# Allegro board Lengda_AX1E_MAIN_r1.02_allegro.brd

Outline 234.8 x 122.7 mm; copper layers: TOP, GND02, ART03, GND04, PWR05, ART06, GND07, BOTTOM. Coordinates in mm from the lower left corner of the outline.

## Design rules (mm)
net group 50OHM: nets EDP_HPD PCH_PWROK
net group AUXN_LVDS: nets AUXN_LVDS EDP_AUX_DN
net group AUXP_LVDS: nets AUXP_LVDS EDP_AUX_DP
net group CL_CLK: nets CL_CLK N1637500
net group CL_DATA: nets CL_DATA N1637496
net group DMIC_CLK1: nets DMIC_CLK1 DMIC_CLK1_PCH
net group EDP_TX_DN<0>: nets EDP_TX_DN<0> TXN0_LVDS
net group EDP_TX_DN<1>: nets EDP_TX_DN<1> TXN1_LVDS
net group EDP_TX_DN<2>: nets EDP_TX_DN<2> N3431626
net group EDP_TX_DN<3>: nets EDP_TX_DN<3> N3431634
net group EDP_TX_DP<0>: nets EDP_TX_DP<0> TXP0_LVDS
net group EDP_TX_DP<1>: nets EDP_TX_DP<1> TXP1_LVDS
net group EDP_TX_DP<2>: nets EDP_TX_DP<2> N3431630
net group EDP_TX_DP<3>: nets EDP_TX_DP<3> N3431638
net group FLASH_SPI_D: nets FLASH_SPI_D<2> FLASH_SPI_D<3>
net group HDMI_CTRLCLK: nets HDMI_CTRLCLK N8275258
net group HDMI_CTRLDATA: nets HDMI_CTRLDATA N8275262
net group HSO: nets HSON HSOP
net group I2C_CLK1: nets I2C_CLK1 SMB_L1CLK_PCH
net group I2C_DATA1: nets I2C_DATA1 SMB_L1DATA_PCH
net group LAN_TX0N: nets LAN_TX0N N2478593
net group LAN_TX0P: nets LAN_TX0P N2478589
net group LAN_TX1N: nets LAN_TX1N N2478581
net group LAN_TX1P: nets LAN_TX1P N2478743
net group LAN_TX2N: nets LAN_TX2N N2478475
net group LAN_TX2P: nets LAN_TX2P N2478981
net group LAN_TX3N: nets LAN_TX3N N2479001
net group LAN_TX3P: nets LAN_TX3P N2478393
net group M_A_CKE: nets M_A_CKE<0> M_A_CKE<1>
net group M_A_CLK_DDR_DN#: nets M_A_CLK_DDR_DN#<0> M_A_CLK_DDR_DN#<1>
net group M_A_CLK_DDR_DP: nets M_A_CLK_DDR_DP<0> M_A_CLK_DDR_DP<1>
net group M_A_CS#: nets M_A_CS#<0> M_A_CS#<1>
net group M_A_ODT: nets M_A_ODT<0> M_A_ODT<1>
net group M_CNV_WR_0_D: nets CNV_WR_0_DN CNV_WR_0_DP
net group M_CNV_WR_1_D: nets CNV_WR_1_DN CNV_WR_1_DP
net group M_CNV_WR_CLK_D: nets CNV_WR_CLK_DN CNV_WR_CLK_DP
net group M_CNV_WT_0_D: nets CNV_WT_0_DN CNV_WT_0_DP
net group M_CNV_WT_1: nets CNV_WT_1_DN CNV_WT_1_DP
net group M_CNV_WT_CLK_D: nets CNV_WT_CLK_DN CNV_WT_CLK_DP
net group M_DDRA_CTL: nets M_0_CSA1_N M_0_CSB0_N
net group M_DDRB_CLK0: nets M_B_CLK_DDR_DN*<0> M_B_CLK_DDR_DP<0>
net group M_GFX_PCIE_CLK_: nets GFX_PCIE_CLK_N GFX_PCIE_CLK_P
net group M_LAN_PCIE_CLK: nets LAN_PCIE_CLK_DN LAN_PCIE_CLK_DP
net group M_PCIE_RX_D_1_WIFI: nets PCIE_RX_DN_9_WIFI PCIE_RX_DP_9_WIFI
net group M_PCIE_RX_D_5_GPU: nets PCIE_RX_DN_5_GPU PCIE_RX_DP_5_GPU
net group M_PCIE_RX_D_6_GPU: nets PCIE_RX_DN_6_GPU PCIE_RX_DP_6_GPU
net group M_PCIE_RX_D_7_GPU: nets PCIE_RX_DN_7_GPU PCIE_RX_DP_7_GPU
net group M_PCIE_RX_D_8_GPU: nets PCIE_RX_DN_8_GPU PCIE_RX_DP_8_GPU
net group M_PCIE_RX_D_9_SSD: nets PCIE_RX_DN_13_SSD PCIE_RX_DP_13_SSD
net group M_PCIE_RX_D_10_SSD: nets PCIE_RX_DN_14_SSD PCIE_RX_DP_14_SSD
net group M_PCIE_RX_D_11_SSD: nets PCIE_RX_DN_15_SSD PCIE_RX_DP_15_SSD
net group M_PCIE_RX_D_12_SSD: nets PCIE_RX_DN_16_SSD PCIE_RX_DP_16_SSD
net group M_PCIE_TX_D_12_SSD: nets PCIE_TX_DN_16_SSD PCIE_TX_DP_16_SSD
net group M_SSD_PCIE_CLK: nets SSD_PCIE_CLK_DN SSD_PCIE_CLK_DP
net group M_SSD_SATA_RX1: nets SSD_SATA_RXN1 SSD_SATA_RXP1
net group M_WIFI_PCIE_CLK: nets WIFI_PCIE_CLK_DN WIFI_PCIE_CLK_DP
net group MDI0: nets MDI0+ MDI0-
net group MDI1: nets MDI1+ MDI1-
net group MDI2: nets MDI2+ MDI2-
net group MDI3: nets MDI3+ MDI3-
net group N2010982: nets N2010982 N4072093
net group N5816815: nets N5816815 N5816861
net group NFC_I2C: nets SMBL0CLK_NFC SMBL0DATA_NFC
net group PCIE_TX_DN<10>: nets N5807743 PCIE_TX_DN<10>
net group PCIE_TX_DN_5_GPU: nets N5765083 PCIE_TX_DN_5_GPU
net group PCIE_TX_DN_6_GPU: nets N5765191 PCIE_TX_DN_6_GPU
net group PCIE_TX_DN_7_GPU: nets N5765627 PCIE_TX_DN_7_GPU
net group PCIE_TX_DN_8_GPU: nets N5765735 PCIE_TX_DN_8_GPU
net group PCIE_TX_DN_9_WIFI: nets N5807759 PCIE_TX_DN_9_WIFI
net group PCIE_TX_DN_13_SSD: nets N5766235 PCIE_TX_DN_13_SSD
net group PCIE_TX_DN_14_SSD: nets N5766259 PCIE_TX_DN_14_SSD
net group PCIE_TX_DN_15_SSD: nets N5766195 PCIE_TX_DN_15_SSD
net group PCIE_TX_DP<10>: nets N5807747 PCIE_TX_DP<10>
net group PCIE_TX_DP_5_GPU: nets N5765087 PCIE_TX_DP_5_GPU
net group PCIE_TX_DP_6_GPU: nets N5765195 PCIE_TX_DP_6_GPU
net group PCIE_TX_DP_7_GPU: nets N5765631 PCIE_TX_DP_7_GPU
net group PCIE_TX_DP_8_GPU: nets N5765739 PCIE_TX_DP_8_GPU
net group PCIE_TX_DP_9_WIFI: nets N5807763 PCIE_TX_DP_9_WIFI
net group PCIE_TX_DP_13_SSD: nets N5766239 PCIE_TX_DP_13_SSD
net group PCIE_TX_DP_14_SSD: nets N5766263 PCIE_TX_DP_14_SSD
net group PCIE_TX_DP_15_SSD: nets N5766199 PCIE_TX_DP_15_SSD
net group POWER: nets +V1P8S +V5S
net group SMB_CLK: nets SMB_CLK SMB_CLK_S2
net group SMB_DATA: nets SMB_DATA SMB_DATA_S2
net group SSD_SATA_RX0: nets N19848541 N19848543
net group SSD_SATA_TX0: nets N19848545 N19848547
net group SSD_SATA_TX1: nets SSD_SATA_TXN1 SSD_SATA_TXP1
net group USB2_DN: nets USB2_DN<1> USB2_DN<3>
net group USB2_DN0_CAM: nets USB2_DN0_CAM USB2_DN<5>
net group USB2_DN<4>: nets N2461749 USB2_DN<4>
net group USB2_DN<7>: nets N2447682 USB2_DN<7>
net group USB2_DN<9>: nets N2465519 USB2_DN<9>
net group USB2_DP: nets USB2_DP<1> USB2_DP<3>
net group USB2_DP0_CAM: nets USB2_DP0_CAM USB2_DP<5>
net group USB2_DP<4>: nets N2461741 USB2_DP<4>
net group USB2_DP<7>: nets N2447742 USB2_DP<7>
net group USB2_DP<9>: nets N2465511 USB2_DP<9>
net group USB3_RX_DN<1>: nets USB3_RX_DN<1> USB3_RX_DN<1>_C
net group USB3_RX_DN<2>: nets USB3_RX_DN<2> USB3_RX_DN<2>_C
net group USB3_RX_DP<1>: nets USB3_RX_DP<1> USB3_RX_DP<1>_C
net group USB3_RX_DP<2>: nets USB3_RX_DP<2> USB3_RX_DP<2>_C
net group USB3_TX_DN<2>_C: nets N2447932 USB3_TX_DN<2>_C
net group USB3_TX_DP<2>_C: nets N2447732 USB3_TX_DP<2>_C
net group DMIC_CLK0: nets DMIC_CLK0 DMIC_CLK0_PCH DMIC_CLK_CODEC N776559
net group DMIC_DATA0: nets DMIC_DATA0 DMIC_DATA0_PCH DMIC_DATA_CODEC N776947
net group DMIC_DATA1: nets DMIC_DATA1 DMIC_DATA1_PCH DMIC_DATA34_CODEC
net group HDA: nets HDA_BITCLK HDA_RST# HDA_SDATAIN0 HDA_SDATAOUT HDA_SYNC
net group HDMI_CLK+: nets HDMI_CLK+ OUT_CLK+ TMDS_CLKP
net group HDMI_CLK-: nets HDMI_CLK- N17228942 OUT_CLK- TMDS_CLKN
net group HDMI_D0+: nets HDMI_D0+ OUT_D0+ TMDS_DATAP0
net group HDMI_D0-: nets HDMI_D0- OUT_D0- TMDS_DATAN0
net group HDMI_D1+: nets HDMI_D1+ OUT_D1+ TMDS_DATAP1
net group HDMI_D1-: nets HDMI_D1- OUT_D1- TMDS_DATAN1
net group HDMI_D2+: nets HDMI_D2+ OUT_D2+ TMDS_DATAP2
net group HDMI_D2-: nets HDMI_D2- OUT_D2- TMDS_DATAN2
net group LCD_BA: nets LCD_BA<1> LCD_BA<2> LCD_BA<GND>
net group M_A_DQ: nets M_A_DQ<0> M_A_DQ<1> M_A_DQ<2> M_A_DQ<3> M_A_DQ<4> M_A_DQ<5> M_A_DQ<6> M_A_DQ<7> M_A_DQ<8> M_A_DQ<9> M_A_DQ<10> M_A_DQ<11> M_A_DQ<12> M_A_DQ<13> M_A_DQ<14> M_A_DQ<15> M_A_DQ<16> M_A_DQ<17> M_A_DQ<18> M_A_DQ<19> M_A_DQ<20> M_A_DQ<21> M_A_DQ<22> M_A_DQ<23> M_A_DQ<24> M_A_DQ<25> M_A_DQ<26> M_A_DQ<27> M_A_DQ<28> M_A_DQ<29> M_A_DQ<30> M_A_DQ<31> M_A_DQ<32> M_A_DQ<33> M_A_DQ<34> M_A_DQ<35> M_A_DQ<36> M_A_DQ<37> M_A_DQ<38> M_A_DQ<39> M_A_DQ<40> M_A_DQ<41> M_A_DQ<42> M_A_DQ<43> M_A_DQ<44> M_A_DQ<45> M_A_DQ<46> M_A_DQ<47> M_A_DQ<48> M_A_DQ<49> M_A_DQ<50> M_A_DQ<51> M_A_DQ<52> M_A_DQ<53> M_A_DQ<54> M_A_DQ<55> M_A_DQ<56> M_A_DQ<57> M_A_DQ<58> M_A_DQ<59> M_A_DQ<60> M_A_DQ<61> M_A_DQ<62> M_A_DQ<63>
net group M_A_DQS_DN#: nets M_A_DQS_DN#<0> M_A_DQS_DN#<1> M_A_DQS_DN#<2> M_A_DQS_DN#<3> M_A_DQS_DN#<4> M_A_DQS_DN#<5> M_A_DQS_DN#<7>
net group M_A_DQS_DP: nets M_A_DQS_DP<0> M_A_DQS_DP<1> M_A_DQS_DP<2> M_A_DQS_DP<3> M_A_DQS_DP<4> M_A_DQS_DP<5> M_A_DQS_DP<6> M_A_DQS_DP<7>
net group M_DDRA_CMD: nets DDR0_A_ALERT_N# DDR0_A_PARITY M_A_A0 M_A_A1 M_A_A2 M_A_A3 M_A_A4 M_A_A5 M_A_A6 M_A_A7 M_A_A8 M_A_A9 M_A_A10 M_A_A11 M_A_A12 M_A_A13 M_A_ACT_N M_A_BG0 M_A_BG1 M_A_BS0 M_A_BS1 M_A_CAS_N M_A_RAS_N M_A_WE_N
net group M_DDRA_DQS6: nets M_A_DQS_DN#<6>
net group M_DDRB_CLK1: nets M_B_CLK_DDR_DN*<1>
net group M_DDRB_CMD: nets DDR1_B_PARITY M_B_A0 M_B_A1 M_B_A2 M_B_A3 M_B_A4 M_B_A5 M_B_A6 M_B_A7 M_B_A8 M_B_A9 M_B_A10 M_B_A11 M_B_A12 M_B_A13 M_B_ACT_N M_B_BG0 M_B_BG1 M_B_BS0 M_B_BS1 M_B_CAS_N M_B_CSA1_N M_B_CSB0_N M_B_RAS_N M_B_WE_N
net group M_DDRB_CTL: nets M_B_CKE<0> M_B_CKE<1> M_B_CLK_DDR_DP<1> M_B_CS*<0> M_B_CS*<1> M_B_ODT<0> M_B_ODT<1>
net group M_DDRB_DATA0: nets M_B_DQ<0> M_B_DQ<1> M_B_DQ<2> M_B_DQ<3> M_B_DQ<4> M_B_DQ<5> M_B_DQ<6> M_B_DQ<7> M_B_DQS_DP<0>
net group M_DDRB_DATA1: nets M_B_DQ<8> M_B_DQ<9> M_B_DQ<10> M_B_DQ<11> M_B_DQ<12> M_B_DQ<13> M_B_DQ<14> M_B_DQ<15> M_B_DQS_DP<1>
net group M_DDRB_DATA2: nets M_B_DQ<16> M_B_DQ<17> M_B_DQ<18> M_B_DQ<19> M_B_DQ<20> M_B_DQ<21> M_B_DQ<22> M_B_DQ<23> M_B_DQS_DP<2>
net group M_DDRB_DATA3: nets M_B_DQ<24> M_B_DQ<25> M_B_DQ<26> M_B_DQ<27> M_B_DQ<28> M_B_DQ<29> M_B_DQ<30> M_B_DQ<31> M_B_DQS_DP<3>
net group M_DDRB_DATA4: nets M_B_DQ<32> M_B_DQ<33> M_B_DQ<34> M_B_DQ<35> M_B_DQ<36> M_B_DQ<37> M_B_DQ<38> M_B_DQ<39> M_B_DQS_DP<4>
net group M_DDRB_DATA5: nets M_B_DQ<40> M_B_DQ<41> M_B_DQ<42> M_B_DQ<43> M_B_DQ<44> M_B_DQ<45> M_B_DQ<46> M_B_DQ<47> M_B_DQS_DP<5>
net group M_DDRB_DATA6: nets M_B_DQ<48> M_B_DQ<49> M_B_DQ<50> M_B_DQ<51> M_B_DQ<52> M_B_DQ<53> M_B_DQ<54> M_B_DQ<55> M_B_DQS_DP<6>
net group M_DDRB_DATA7: nets M_B_DQ<56> M_B_DQ<57> M_B_DQ<58> M_B_DQ<59> M_B_DQ<60> M_B_DQ<61> M_B_DQ<62> M_B_DQ<63> M_B_DQS_DP<7>
net group M_DDRB_DQS0: nets M_B_DQS_DN*<0>
net group M_DDRB_DQS1: nets M_B_DQS_DN*<1>
net group M_DDRB_DQS2: nets M_B_DQS_DN*<2>
net group M_DDRB_DQS3: nets M_B_DQS_DN*<3>
net group M_DDRB_DQS4: nets M_B_DQS_DN*<4>
net group M_DDRB_DQS5: nets M_B_DQS_DN*<5>
net group M_DDRB_DQS6: nets M_B_DQS_DN*<6>
net group M_DDRB_DQS7: nets M_B_DQS_DN*<7>
net group M_LAO: nets LAO_CLKP LAO_DATAP0 LAO_DATAP1 LAO_DATAP2 LAO_DATAP3
net group M_LAO1: nets LAO1_CLKP LAO1_DATAP0 LAO1_DATAP1 LAO1_DATAP2 LAO1_DATAP3
net group M_LAO1_CLK: nets LAO1_CLKN
net group M_LAO1_DATA0: nets LAO1_DATAN0
net group M_LAO1_DATA1: nets LAO1_DATAN1
net group M_LAO1_DATA2: nets LAO1_DATAN2
net group M_LAO1_DATA3: nets LAO1_DATAN3
net group M_LAO_CLK: nets LAO_CLKN
net group M_LAO_DATA0: nets LAO_DATAN0
net group M_LAO_DATA1: nets LAO_DATAN1
net group M_LAO_DATA2: nets LAO_DATAN2
net group M_LAO_DATA3: nets LAO_DATAN3
net group PCIE: nets PLT_RST_BUF#
net group PCIE_RX_DN: nets PCIE_RX_DN<10>
net group PCIE_RX_DP: nets PCIE_RX_DP<10>
net group USB2_OC: nets USB2_OC<0> USB2_OC<1> USB2_OC<2> USB2_OC<3>
net group USB3_TX_DN: nets USB3_TX_DN<2>
net group USB3_TX_DN<1>: nets N1170323 USB3_TX_DN<1> USB3_TX_DN<1>_C
net group USB3_TX_DP: nets USB3_TX_DP<2>
net group USB3_TX_DP<1>: nets N1170159 USB3_TX_DP<1> USB3_TX_DP<1>_C
nets with their own width: min track width 0.203; nets GND

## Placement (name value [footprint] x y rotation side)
ACN1  WB1012US-02T5  [SMD-CN-100P-2N-V-CB]  155.78 112.13 90 top
C1  20PF  [CC0402N]  66.65 71.65 180 bottom
C2  1uF  [CC0402N]  155.92 92.15 0 top
C3  220nF  [CC0402N]  220.99 51.78 0 bottom
C4  1uF  [CC0402N]  155.86 94.8 270 top
C5  0.1uF  [CC0402N]  161.27 94.85 270 top
C6  10uF  [CC0603N]  32.05 68.8 0 top
C7  47UF  [CAE630W570HN]  123.97 64.68 0 top
C8  1uF  [CC0402N]  48.41 58.97 90 bottom
C9  0.1uF  [CC0402N]  49.64 58.97 270 bottom
C10  0.1uF  [CC0402N]  160.65 92.17 90 top
C11  15pF  [CC0402N]  164.63 85.57 270 top
C12  220nF  [CC0402N]  220.99 50.95 0 bottom
C13  15pF  [CC0402N]  165.89 85.56 270 top
C14  1uF  [CC0603N]  167.92 65.52 90 bottom
C15  1uF  [CC0603N]  167.11 57.89 270 bottom
C16  22uF  [CC0603N]  92 74.97 0 top
C17  0.1uF  [CC0402N]  88.24 86.82 0 top
C18  0.1uF  [CC0402N]  91.91 73.97 0 top
C19  100uF  [CAE660W800HN]  101.87 91.44 90 top
C20  4.7UF  [CC0603N]  94.85 85.24 270 top
C21  1uF  [CC0402N]  168.23 95.88 270 bottom
C22  1uF  [CC0402N]  213.21 71.15 180 bottom
C23  0.1uF  [CC0402N]  88.97 88.82 180 top
C24  0.1uF  [CC0402N]  88.97 89.59 180 top
C25  0.1uF  [CC0402N]  91.82 89.74 90 top
C26  4.7UF  [CC0603N]  90.47 89.99 270 top
C27  0.1uF  [CC0402N]  82.46 88.04 270 top
C28  0.1uF  [CC0402N]  83.24 93.09 90 top
C29  1uF  [CC0603N]  83.19 90.84 90 top
C30  1uF  [CC0402N]  92.6 89.74 270 top
C31  0.1uF  [CC0402N]  126.64 77.29 270 top
C32  22uF  [CC0603N]  134.78 82.22 90 bottom
C33  0.1uF  [CC0402N]  132.57 82.17 90 bottom
C34  22uF  [CC0603N]  179.04 98.7 90 bottom
C35  22uF  [CC0603N]  177.84 98.7 90 bottom
C36  22uF  [CC0603N]  169.25 90.14 180 bottom
C37  22uF  [CC0603N]  169.24 91.35 180 bottom
C38  22uF  [CC0603N]  178.24 100.48 90 top
C39  22uF  [CC0603N]  179.49 100.54 90 top
C40  22uF  [CC0603N]  199.8 85.84 90 bottom
C41  22uF  [CC0603N]  201.08 88.98 90 top
C42  22uF  [CC0603N]  202.44 88.97 90 top
C43  2.2uF  [CC0603N]  164.65 95.08 180 top
C44  0.1uF  [CC0402N]  165.01 94.06 180 top
C45  22uF  [CC0603N]  164.64 93.03 180 top
C46  18pF  [CC0402N]  171.94 58.4 270 bottom
C47  18pF  [CC0402N]  171.94 60.16 90 bottom
C48  22nF  [CC0402N]  218.23 62.88 0 bottom
C49  10UF  [CC0603N]  229.92 18.77 0 bottom
C50  0.1uF  [CC0402N]  155.95 86.68 0 top
C51  10uF  [CC0603N]  71.65 57.15 270 bottom
C52  10uF  [CC0603N]  76.21 58.6 270 bottom
C53  0.1uF  [CC0402N]  77.25 58.72 270 bottom
C54  22uF  [CC0603N]  184.96 90.8 0 bottom
C55  10uF  [CC0603N]  128.27 110.32 90 top
C56  0.1uF  [CC0402N]  130.06 110.38 270 top
C57  0.1uF  [CC0402N]  129.29 110.38 270 top
C58  10UF  [CC0603N]  128.94 89.86 270 top
C59  22uF  [CC0603N]  183.5 85.32 270 bottom
C60  220nF  [CC0402N]  220.92 49.42 0 bottom
C61  220nF  [CC0402N]  220.92 48.61 0 bottom
C62  220nF  [CC0402N]  220.96 46.21 0 bottom
C63  22uF  [CC0603N]  232.01 76.31 0 bottom
C64  0.1uF  [CC0402N]  132.18 86.36 0 top
C65  0.1uF  [CC0402N]  132.18 87.13 0 top
C66  220nF  [CC0402N]  220.95 45.41 0 bottom
C67  220nF  [CC0402N]  220.9 43.78 0 bottom
C68  10UF  [CC0603N]  45.24 83.49 270 bottom
C69  10UF  [CC0603N]  46.49 83.49 270 bottom
C70  0.1uF  [CC0402N]  45.4 79.81 90 bottom
C71  0.1uF  [CC0402N]  179.97 90.16 90 top
C72  0.1uF  [CC0402N]  179.19 90.16 90 top
C73  220nF  [CC0402N]  111.55 72.2 180 top
C74  220nF  [CC0402N]  111.55 71.43 180 top
C75  10UF  [CC0603N]  54.62 103.78 0 bottom
C76  10UF  [CC0603N]  54.38 94.61 90 bottom
C77  220nF  [CC0402N]  111.55 69.75 180 top
C78  220nF  [CC0402N]  111.55 68.96 180 top
C79  220nF  [CC0402N]  111.55 67.35 180 top
C80  0.1uF  [CC0402N]  130.71 89.99 90 top
C81  220nF  [CC0402N]  111.55 66.57 180 top
C82  10UF  [CC0603N]  55.66 94.61 90 bottom
C83  0.01uF  [CC0402N]  54.65 102.77 0 bottom
C84  10UF  [CC0603N]  57.9 111.81 90 top
C85  22nF  [CC0402N]  215.68 65.97 180 bottom
C86  10UF  [CC0603N]  115.08 50.74 90 bottom
C87  10UF  [CC0603N]  229.91 17.46 0 bottom
C88  0.1uF  [CC0402N]  98.32 55.4 90 top
C90  0.1uF  [CC0402N]  129.94 89.98 90 top
C104  22uF  [CC0603N]  155 84.88 270 top
C114  0.1uF  [CC0402N]  158.29 91.53 180 top
C118  0.1uF  [CC0402N]  124.07 60.55 0 top
C122  2.2uF  [CC0603N]  199.09 92.09 270 top
C123  0.1uF  [CC0402N]  198.07 92.37 270 top
C124  2.2uF  [CC0603N]  186.39 97.2 180 bottom
C125  0.1uF  [CC0402N]  185.62 81.79 90 bottom
C126  2.2uF  [CC0603N]  194.18 97.7 90 bottom
C127  1uF  [CC0402N]  159.96 50.18 90 bottom
C128  0.01uF  [CC0402N]  162.7 53.26 180 bottom
C129  4.7UF  [CC0603N]  116.18 63.58 180 top
C130  0.1uF  [CC0402N]  121.94 55.27 0 bottom
C131  0.1uF  [CC0402N]  113.87 50.98 90 bottom
C132  22uF  [CC0603N]  143.78 55.15 90 bottom
C133  220nF  [CC0402N]  220.9 42.98 0 bottom
C134  22uF  [CC0603N]  142.55 55.16 90 bottom
C135  0.1uF  [CC0402N]  197.79 70.66 270 bottom
C136  1uF  [CC0402N]  165.88 68.91 270 bottom
C137  1uF  [CC0402N]  229.69 19.77 180 bottom
C138  1uF  [CC0402N]  229.7 20.58 180 bottom
C139  100NF  [CC0402N]  224.49 9.23 90 top
C140  22uF  [CC0603N]  141.99 54.84 90 top
C141  2.2uF  [CC0603N]  223.48 8.96 90 top
C142  100NF  [CC0402N]  199.98 18.88 180 bottom
C143  10uF  [CC0603N]  118.83 89.21 270 bottom
C144  0.1uF  [CC0402N]  119.83 89.23 90 bottom
C145  0.01uF  [CC0402N]  15.01 110.48 270 top
C146  0.01uF  [CC0402N]  122.4 87.61 180 bottom
C147  10uF  [CC0603N]  125.89 90.04 270 bottom
C152  0.1uF  [CC0402N]  58.7 28.25 0 bottom
C153  0.1uF  [CC0402N]  58.7 29.04 0 bottom
C154  0.1uF  [CC0402N]  58.7 24.74 0 bottom
C155  0.1uF  [CC0402N]  58.7 25.53 0 bottom
C156  2.2uF  [CC0603N]  202.59 21.46 180 bottom
C157  100NF  [CC0402N]  182.34 21.83 0 bottom
C158  22uF  [CC0603N]  154.77 94.76 90 top
C159  22uF  [CC0603N]  152.3 94.76 90 top
C160  22uF  [CC0603N]  153.52 94.76 90 top
C161  10UF  [CC0603N]  176.53 14.96 90 bottom
C162  10UF  [CC0603N]  221.46 14.73 90 bottom
C163  10UF  [CC0603N]  213.69 14.96 90 bottom
C164  10UF  [CC0603N]  185.76 19.36 0 bottom
C165  10UF  [CC0603N]  167.11 14.91 90 bottom
C166  10UF  [CC0603N]  186.62 13.79 0 bottom
C167  10UF  [CC0603N]  171.81 19.1 90 bottom
C168  10UF  [CC0603N]  202.44 14.09 270 bottom
C169  1uF  [CC0402N]  182.38 19.22 90 bottom
C170  1uF  [CC0402N]  200.54 18.03 180 bottom
C171  1uF  [CC0402N]  175.34 18.77 270 bottom
C172  1uF  [CC0402N]  168.17 18.83 270 bottom
C173  1uF  [CC0402N]  172.98 14.79 90 bottom
C174  1uF  [CC0402N]  160.74 19.03 270 bottom
C175  1uF  [CC0402N]  195.93 17.96 90 bottom
C176  1uF  [CC0402N]  181.8 15.68 90 bottom
C177  10UF  [CC0603N]  224.87 22.52 0 bottom
C178  100NF  [CC0402N]  225.19 25.19 0 bottom
C179  100NF  [CC0402N]  225.19 23.57 0 bottom
C180  100NF  [CC0402N]  225.19 26 0 bottom
C181  100NF  [CC0402N]  225.17 24.37 0 bottom
C183  22uF  [CC0603N]  231.99 75.1 0 top
C184  22uF  [CC0603N]  192.11 92.12 270 top
C185  0.1uF  [CC0402N]  94.45 105.66 180 top
C187  0.1uF  [CC0402N]  61.69 31.07 0 bottom
C188  4.7UF  [CC0603N]  108.85 106.08 270 top
C189  4.7UF  [CC0603N]  107.6 106.06 270 top
C190  0.1uF  [CC0402N]  110.36 105.1 180 top
C191  0.01uF  [CC0402N]  76.04 61.13 90 bottom
C192  4.7UF  [CC0603N]  166.58 71.59 0 bottom
C193  22uF  [CC0603N]  145.01 55.12 90 bottom
C194  0.1uF  [CC0402N]  146.12 55.11 90 bottom
C195  1uF  [CC0402N]  113.4 57.38 270 bottom
C196  0.1uF  [CC0402N]  61.69 30.26 0 bottom
C197  0.1uF  [CC0402N]  110.92 50.85 180 bottom
C198  1uF  [CC0402N]  177.34 68.37 180 bottom
C199  100pF  [CC0402N]  110.85 48.8 180 bottom
C200  10uF  [CC0603N]  167.1 81.25 180 bottom
C201  22uF  [CC0603N]  184.9 92.15 0 bottom
C202  22uF  [CC0603N]  182.93 98.07 90 bottom
C205  10UF  [CC0603N]  144.32 75.72 270 top
C207  0.1uF  [CC0402N]  145.35 75.49 270 top
C209  10UF  [CC0603N]  149.7 72.69 270 top
C210  0.1uF  [CC0402N]  150.73 72.56 270 top
C211  10UF  [CC0603N]  221.44 8.33 270 bottom
C212  10UF  [CC0603N]  222.73 8.33 270 bottom
C213  0.1uF  [CC0402N]  223.77 8.29 270 bottom
C214  10UF  [CC0603N]  211.8 8.95 180 bottom
C215  0.1uF  [CC0402N]  164.52 53.24 180 bottom
C216  1uF  [CC0402N]  165.49 51.76 270 bottom
C217  10UF  [CC0603N]  127.48 70.97 0 bottom
C218  0.01uF  [CC0402N]  125.54 68.37 180 bottom
C219  10UF  [CC0603N]  125.57 69.42 0 bottom
C220  0.01uF  [CC0402N]  91.02 68.84 180 top
C222  10UF  [CC0603N]  91.09 69.97 0 top
C223  10UF  [CC0603N]  92.01 76.18 0 top
C224  0.01uF  [CC0402N]  119.22 68.72 0 bottom
C225  0.01uF  [CC0402N]  92 72.21 180 top
C226  10UF  [CC0603N]  133.57 82.22 90 bottom
C228  0.1uF  [CC0402N]  88.4 107.89 180 top
C229  0.1uF  [CC0402N]  86.73 108.37 90 top
C230  0.1uF  [CC0402N]  60.22 108.01 0 top
C231  0.1uF  [CC0402N]  62.72 107.94 0 top
C232  0.1uF  [CC0402N]  61.98 89.49 180 top
C233  0.1uF  [CC0402N]  21.28 91.79 270 bottom
C234  0.1uF  [CC0402N]  20.5 91.79 270 bottom
C235  22uF  [CC0603N]  180.45 97.99 90 bottom
C237  10uF  [CC0603N]  176.6 98.71 90 bottom
C238  10uF  [CC0603N]  180.71 85.55 270 bottom
C239  10uF  [CC0603N]  182.02 80.17 270 bottom
C240  10uF  [CC0603N]  175.37 98.72 90 bottom
C241  10uF  [CC0603N]  176.27 79.84 270 bottom
C242  10uF  [CC0603N]  169.56 88.83 180 bottom
C243  10UF  [CC0603N]  184.91 95.96 0 bottom
C244  10UF  [CC0603N]  178.5 85.57 270 bottom
C245  10UF  [CC0603N]  169.58 87.59 180 bottom
C246  10UF  [CC0603N]  180.75 80.18 270 bottom
C247  10UF  [CC0603N]  169.26 83.75 180 bottom
C248  10UF  [CC0603N]  169.69 86.2 180 bottom
C249  10UF  [CC0603N]  169.29 84.98 180 bottom
C250  10UF  [CC0603N]  184.96 89.6 0 bottom
C251  10UF  [CC0603N]  169.26 82.52 180 bottom
C252  100pF  [CC0402N]  179.71 79.95 90 bottom
C253  12pF  [CC0402N]  178.7 79.91 90 bottom
C254  0.1uF  [CC0402N]  177.78 79.84 90 bottom
C255  10uF  [CC0603N]  181.67 98 90 bottom
C256  10UF  [CC0603N]  174.13 98.72 90 bottom
C257  10UF  [CC0603N]  172.87 98.72 90 bottom
C258  10UF  [CC0603N]  198.67 80.68 270 bottom
C259  10UF  [CC0603N]  199.9 80.69 270 bottom
C260  10UF  [CC0603N]  197.36 80.68 270 bottom
C261  10UF  [CC0603N]  196.15 80.73 270 bottom
C262  0.1uF  [CC0402N]  160.09 90.38 270 top
C263  10UF  [CC0603N]  95.13 72.36 0 top
C264  10UF  [CC0603N]  95.13 73.58 0 top
C265  10UF  [CC0603N]  196.22 83.76 180 bottom
C266  10UF  [CC0603N]  210.35 79.19 90 bottom
C267  10UF  [CC0603N]  208.39 78.5 180 bottom
C268  10UF  [CC0603N]  184.89 93.46 0 bottom
C269  10UF  [CC0603N]  184.9 94.74 0 bottom
C270  1uF  [CC0402N]  185.52 84.31 180 bottom
C271  47uF  [CC0805N]  186.19 85.51 180 bottom
C272  10UF  [CC0603N]  193.34 80.71 90 bottom
C273  10UF  [CC0603N]  192.11 80.71 90 bottom
C274  1uF  [CC0402N]  211.68 69.39 270 bottom
C275  22uF  [CC0603N]  203.7 58.39 270 bottom
C276  22uF  [CC0603N]  209.96 58.28 270 bottom
C277  220nF  [CC0402N]  178.41 90.16 270 top
C278  220nF  [CC0402N]  177.64 90.16 270 top
C279  10uF  [CC0603N]  24.79 85.64 0 top
C280  22uF  [CC0603N]  206.48 58.39 270 bottom
C281  0.1uF  [CC0402N]  160.29 88.67 180 top
C282  10uF  [CC0603N]  35.83 68.67 0 top
C283  10UF  [CC0603N]  198.55 58.34 270 bottom
C284  10UF  [CC0603N]  189.73 68.63 180 bottom
C285  10UF  [CC0603N]  190.86 58.2 270 bottom
C286  10UF  [CC0603N]  193.38 58.33 270 bottom
C287  10UF  [CC0603N]  201.3 58.47 270 bottom
C288  1uF  [CC0402N]  196.44 68.65 180 bottom
C289  1uF  [CC0402N]  186.81 59.83 270 bottom
C290  1uF  [CC0402N]  209.54 62.94 90 bottom
C291  10uF  [CC0603N]  232.08 86.33 0 bottom
C295  0.1uF  [CC0402N]  156.98 87.6 180 top
C296  1uF  [CC0402N]  204.46 63.01 90 bottom
C297  1uF  [CC0402N]  194.52 62.94 90 bottom
C298  1uF  [CC0402N]  207.13 62.94 90 bottom
C299  12pF  [CC0402N]  199.51 63.01 270 bottom
C300  12pF  [CC0402N]  202.02 63.08 270 bottom
C301  12pF  [CC0402N]  196.97 62.94 270 bottom
C302  12pF  [CC0402N]  190.9 60.85 0 bottom
C303  12pF  [CC0402N]  199.26 68.58 0 bottom
C304  12pF  [CC0402N]  209.87 61.44 180 bottom
C305  1uF  [CC0402N]  187.06 62.94 90 bottom
C306  1uF  [CC0402N]  188.9 62.92 90 bottom
C307  1uF  [CC0402N]  189.91 62.92 90 bottom
C308  0.1uF  [CC0402N]  166.68 68.91 270 bottom
C309  1uF  [CC0402N]  197.36 61.38 0 bottom
C310  1uF  [CC0402N]  188.62 61.19 180 bottom
C311  1uF  [CC0402N]  212.08 62.82 90 bottom
C312  1uF  [CC0402N]  202 68.61 180 bottom
C313  22uF  [CC0603N]  179.91 77.65 180 bottom
C314  22uF  [CC0603N]  197.02 92.53 270 top
C315  22uF  [CC0603N]  195.81 92.52 270 top
C316  1uF  [CC0402N]  198.57 70.66 90 bottom
C317  1uF  [CC0402N]  193.15 68.61 0 bottom
C318  1uF  [CC0402N]  211.1 58.97 315 top
C319  1uF  [CC0402N]  205.27 61.21 0 bottom
C320  1uF  [CC0402N]  207.59 59.66 315 top
C321  1uF  [CC0402N]  202.22 59.81 270 top
C322  10UF  [CC0603N]  43.53 109.65 90 top
C323  10UF  [CC0603N]  35.51 109.98 90 top
C324  10UF  [CC0603N]  99.27 81.51 270 top
C325  1uF  [CC0402N]  213.59 59.78 315 top
C326  1uF  [CC0402N]  199.79 59.41 270 top
C327  1uF  [CC0402N]  197.31 59.85 270 top
C328  1uF  [CC0402N]  194.77 59.8 270 top
C329  1uF  [CC0402N]  192.13 59.78 270 top
C330  10UF  [CC0603N]  100.49 81.52 270 top
C331  1uF  [CC0402N]  125.07 77.31 90 top
C332  1000pF  [CC0402N]  123.51 77.31 270 top
C333  1uF  [CC0402N]  121.98 77.31 90 top
C334  1uF  [CC0402N]  189.75 59.81 270 top
C335  0.1uF  [CC0402N]  143.22 96.82 270 top
C336  22uF  [CC0603N]  149.97 84.92 270 top
C337  1uF  [CC0603N]  32.05 70.33 180 top
C338  22uF  [CC0603N]  151.21 84.93 270 top
C339  1uF  [CC0603N]  24.79 86.86 180 top
C340  0.1uF  [CC0402N]  40.71 59.87 180 top
C341  0.1uF  [CC0402N]  59.09 75.09 90 top
C342  47pF  [CC0402N]  38.98 61.71 270 top
C343  22uF  [CC0603N]  152.47 84.94 270 top
C344  22uF  [CC0603N]  153.72 84.94 270 top
C345  4.7UF  [CC0603N]  150.65 95.35 270 top
C346  4.7UF  [CC0603N]  149.41 95.35 270 top
C347  1uF  [CC0402N]  186.54 59.93 270 top
C348  1uF  [CC0402N]  184.56 59.93 270 top
C349  1uF  [CC0402N]  144.26 100.25 270 top
C350  1uF  [CC0402N]  150.81 99.97 270 top
C351  1000pF  [CC0402N]  146.59 100.25 90 top
C352  1uF  [CC0402N]  147.38 100.25 270 top
C353  1uF  [CC0402N]  181.95 58.08 270 bottom
C354  1uF  [CC0402N]  162.83 94.85 90 top
C355  1uF  [CC0402N]  162.05 94.85 90 top
C356  1uF  [CC0402N]  160.88 90.39 90 top
C357  1uF  [CC0402N]  163.26 91.51 0 top
C358  1uF  [CC0402N]  174.24 75.47 270 bottom
C359  1uF  [CC0402N]  174.89 68.72 90 bottom
C360  0.1uF  [CC0402N]  172.13 68.25 90 bottom
C361  1uF  [CC0402N]  200.18 70.68 90 bottom
C362  1uF  [CC0402N]  186.83 68.83 90 bottom
C363  1uF  [CC0402N]  224.19 70.59 90 top
C364  1uF  [CC0402N]  224.99 70.56 90 top
C365  1uF  [CC0402N]  199.39 70.67 90 bottom
C366  1uF  [CC0402N]  214.21 79.96 270 bottom
C367  0.1uF  [CC0402N]  50.49 80.51 90 top
C368  0.1uF  [CC0402N]  51.26 80.51 90 top
C369  0.1uF  [CC0402N]  53.02 80.51 90 top
C370  0.1uF  [CC0402N]  53.79 80.51 90 top
C371  0.1uF  [CC0402N]  55.56 80.51 90 top
C372  0.1uF  [CC0402N]  56.33 80.51 90 top
C373  0.1uF  [CC0402N]  58.08 80.51 90 top
C374  0.1uF  [CC0402N]  58.85 80.51 90 top
C375  1uF  [CC0603N]  35.83 67.46 180 top
C376  4.7UF  [CC0603N]  28.11 86.67 90 top
C377  1uF  [CC0402N]  201 70.66 90 bottom
C378  4.7UF  [CC0603N]  26.89 86.67 90 top
C379  15pF  [CC0402N]  203.12 78.24 90 bottom
C380  1uF  [CC0402N]  191.72 70.68 90 bottom
C381  4.7UF  [CC0603N]  116.22 62.2 180 top
C382  10UF  [CC0603N]  36.71 109.98 90 top
C383  1uF  [CC0402N]  226.64 70.56 90 top
C384  1uF  [CC0402N]  192.48 70.67 90 bottom
C385  0.01uF  [CC0402N]  42.54 109.94 90 top
C386  0.1uF  [CC0402N]  32.06 91.69 270 bottom
C387  0.1uF  [CC0402N]  31.25 91.69 270 bottom
C388  1uF  [CC0402N]  216.04 82.94 0 bottom
C389  15pF  [CC0402N]  202.34 78.24 90 bottom
C390  10UF  [CC0603N]  141.07 48.34 90 top
C391  22uF  [CC0603N]  201.86 97.9 90 bottom
C392  22uF  [CC0603N]  195.73 97.75 90 bottom
C393  10UF  [CC0603N]  142.31 48.34 90 top
C394  0.01uF  [CC0402N]  127.1 73.31 180 bottom
C395  10UF  [CC0603N]  127.48 72.22 0 bottom
C396  0.1uF  [CC0402N]  146.46 70.51 0 top
C397  22uF  [CC0603N]  212.19 97.68 90 bottom
C398  1uF  [CC0402N]  147.34 75.2 0 top
C399  0.01uF  [CC0402N]  145.81 72.9 90 top
C400  1uF  [CC0402N]  147.23 69.67 0 top
C401  0.01uF  [CC0402N]  119.83 74.21 0 bottom
C402  22uF  [CC0603N]  231.98 71.28 0 bottom
C403  22uF  [CC0603N]  179.92 76.31 180 bottom
C404  22uF  [CC0603N]  231.98 73.84 0 bottom
C405  15pF  [CC0402N]  201.56 78.24 90 bottom
C406  15pF  [CC0402N]  197.33 78.28 90 bottom
C407  10UF  [CC0603N]  51.09 111.39 90 top
C408  0.1uF  [CC0402N]  92.93 106.9 270 top
C409  0.1uF  [CC0402N]  94.45 106.45 180 top
C410  10UF  [CC0603N]  49.88 111.39 90 top
C411  0.1uF  [CC0402N]  212.25 9.95 180 bottom
C412  0.01uF  [CC0402N]  56.89 111.61 90 top
C413  20PF  [CC0402N]  66.65 70.43 180 bottom
C414  10uF  [CC0603N]  72.88 57.16 270 bottom
C415  0.1uF  [CC0402N]  70.2 61.83 90 bottom
C416  0.1uF  [CC0402N]  77.22 72.85 0 bottom
C417  0.1uF  [CC0402N]  77.22 72.07 0 bottom
C418  0.1uF  [CC0402N]  69.87 74.33 90 bottom
C419  0.1uF  [CC0402N]  70.2 57.36 270 bottom
C420  4.7uF  [CC0603N]  69.92 63.91 180 bottom
C421  0.1uF  [CC0402N]  69.91 65.94 270 bottom
C422  0.1uF  [CC0402N]  77.52 67.05 180 bottom
C423  0.1uF  [CC0402N]  77.52 67.87 180 bottom
C424  0.1uF  [CC0402N]  74.23 74.93 90 bottom
C425  0.1uF  [CC0402N]  75.8 74.92 90 bottom
C426  0.1uF  [CC0402N]  66.65 73.2 180 bottom
C427  0.1uF  [CC0402N]  63.02 67.88 180 bottom
C428  0.1uF  [CC0402N]  75 74.93 90 bottom
C429  22pF  [CC0402N]  38.18 83.13 90 top
C430  22pF  [CC0402N]  38.79 81.86 0 top
C431  22pF  [CC0402N]  35.66 79.78 180 top
C432  0.1uF  [CC0402N]  33.79 63.66 180 top
C433  0.1uF  [CC0402N]  66.65 72.43 180 bottom
C434  0.1uF  [CC0402N]  71.52 74.95 90 bottom
C435  4.7uF  [CC0603N]  63.01 66.08 0 bottom
C436  0.1uF  [CC0402N]  63.01 67.1 180 bottom
C437  1uF  [CC0402N]  71.45 65.94 90 bottom
C438  0.1uF  [CC0402N]  70.68 65.94 270 bottom
C439  15pF  [CC0402N]  196.55 78.28 90 bottom
C440  0.1uF  [CC0402N]  83.14 91.74 90 bottom
C441  0.01uF  [CC0402N]  80.94 91.74 270 bottom
C442  1000pF  [CC1206N]  80.93 91.71 270 bottom
C443  1000pF  [CC0402N]  82.35 91.74 90 bottom
C444  10UF  [CC0603N]  23.71 59.81 0 top
C445  0.1uF  [CC0402N]  23.7 60.8 180 top
C446  10UF  [CC0603N]  23.71 58.6 0 top
C449  0.1uF  [CC0402N]  233.17 52.69 90 top
C450  4.7UF  [CC0603N]  233.1 20.42 0 bottom
C451  0.01uF  [CC0402N]  20.36 42.71 180 top
C452  0.01uF  [CC0402N]  20.36 43.5 180 top
C453  0.01uF  [CC0402N]  20.4 46.55 180 top
C454  0.01uF  [CC0402N]  20.4 47.35 180 top
C455  4.7UF  [CC0603N]  233.15 27.58 0 bottom
C456  2.2uF  [CC0603N]  23.64 81.84 0 top
C457  2.2uF  [CC0603N]  24.89 77.42 180 top
C458  10UF  [CC0603N]  23.64 83.07 180 top
C459  0.1uF  [CC0603N]  233.15 28.79 180 bottom
C461  10UF  [CC0603N]  25.12 74.15 90 top
C462  0.1uF  [CC0402N]  24.67 76.22 0 top
C463  0.1uF  [CC0402N]  26.63 83.13 270 top
C464  10UF  [CC0603N]  24.4 84.3 0 top
C465  2.2uF  [CC0603N]  230.52 101.64 0 bottom
C467  1uF  [CC0603N]  22.69 75.44 270 top
C468  0.1uF  [CC0402N]  27.97 74.92 0 top
C469  10UF  [CC0603N]  28.3 73.92 180 top
C470  4.7UF  [CC0603N]  30.54 86.67 90 top
C471  4.7UF  [CC0603N]  29.3 86.67 90 top
C472  10UF  [CC0603N]  26.34 74.15 90 top
C473  0.1uF  [CC0603N]  232.49 35.23 180 top
C474  0.1uF  [CC0603N]  232.49 36.44 180 top
C475  10UF  [CC0603N]  33.01 87.74 270 top
C476  0.1uF  [CC0402N]  30.15 75.14 180 top
C477  10UF  [CC0603N]  30.54 72.74 90 top
C478  100pF  [CC0402N]  32.88 90.89 270 top
C479  0.1uF  [CC0402N]  34.1 87.43 270 top
C480  0.1uF  [CC0402N]  32.17 75.14 0 top
C481  10UF  [CC0603N]  32.17 72.75 90 top
C482  10UF  [CC0603N]  35.71 75.52 0 top
C483  0.1uF  [CC0402N]  35.44 76.51 180 top
C484  10UF  [CC0603N]  36.35 83.08 0 top
C485  0.1uF  [CC0402N]  35.89 82.09 180 top
C486  10pF  [CC0402N]  37.07 77.56 270 top
C487  10UF  [CC0603N]  36.36 80.91 180 top
C488  22pF  [CC0402N]  38.6 79.7 270 top
C491  0.1uF  [CC0402N]  232.59 43.61 270 top
C493  4.7UF  [CC0603N]  229.68 60.96 180 bottom
C494  0.1uF  [CC0603N]  232.96 63.11 180 bottom
C495  0.1uF  [CC0603N]  232.96 61.86 180 bottom
C496  10uF  [CC1210N]  55.06 45.21 180 top
C497  10uF  [CC1210N]  55.06 42.21 180 top
C499  100pF  [CC0402N]  21.77 87.02 180 top
C500  100pF  [CC0402N]  19.6 87.01 0 top
C501  100pF  [CC0402N]  12.08 92.96 270 top
C502  100pF  [CC0402N]  8.25 92.13 270 bottom
C503  0.1uF  [CC0603N]  54.29 39.41 0 top
C504  4.7uF  [CC1206N]  67.36 20.96 0 top
C505  10uF  [CC1210N]  67.36 24.85 0 top
C506  10uF  [CC5750N]  67.36 24.82 0 top
C507  0.1uF  [CC0402N]  31.47 51.61 180 bottom
C509  0.47uF  [CC0402N]  34.59 45.8 180 bottom
C512  2.2uF  [CC0402N]  33.33 47.85 180 bottom
C513  15pF  [CC0402N]  200.78 78.25 90 bottom
C514  0.1uF  [CC0402N]  56.19 15.07 180 bottom
C515  10UF  [CC0603N]  56.16 13.24 0 bottom
C516  15pF  [CC0402N]  195.77 78.29 90 bottom
C517  10UF  [CC0603N]  59.18 13.24 0 bottom
C518  0.01uF  [CC0402N]  55.07 10.43 90 bottom
C519  15pF  [CC0402N]  194.99 78.3 90 bottom
C520  0.1uF  [CC0402N]  57.4 9.83 0 bottom
C521  10uF  [CC0603N]  116.99 49.34 270 bottom
C522  1uF  [CC0603N]  118.26 49.34 270 bottom
C524  0.1uF  [CC0402N]  126.16 52.98 270 bottom
C525  10uF  [CC0603N]  125.16 52.86 90 bottom
C526  0.1uF  [CC0402N]  215.17 101.46 180 bottom
C531  0.1uF  [CC0402N]  52.54 30.73 270 bottom
C532  0.1uF  [CC0402N]  52.56 30.73 270 top
C534  2.2uF  [CC0603N]  65.24 25.14 180 bottom
C535  1uF  [CC0402N]  58.66 22.37 180 bottom
C536  0.1uF  [CC0402N]  61.06 18.5 270 bottom
C537  0.1uF  [CC0402N]  56.19 14.27 180 bottom
C540  0.1uF  [CC0402N]  47.2 26.39 0 bottom
C541  1uF  [CC0402N]  58.01 26.86 270 bottom
C542  0.1uF  [CC0402N]  59.3 26.86 270 bottom
C543  0.01uF  [CC0402N]  60.08 26.86 270 bottom
C544  10UF  [CC0603N]  58.32 20.26 270 bottom
C545  0.1uF  [CC0402N]  56.64 32.37 270 top
C546  0.1uF  [CC0402N]  48.09 16.64 0 bottom
C547  10uF  [CC0603N]  48.01 17.66 180 bottom
C548  10UF  [CC0603N]  52.53 17.7 180 bottom
C549  0.1uF  [CC0402N]  52.94 19.15 0 bottom
C550  0.01uF  [CC0402N]  52.94 19.94 0 bottom
C634  10uF  [CC0603N]  25.49 56.63 270 top
C635  1uF  [CC0603N]  24.27 56.62 90 top
C640  0.1uF  [CC0402N]  232.67 15.89 180 top
C641  0.1uF  [CC0402N]  232.77 26.72 0 top
C642  1000pF  [CC0402N]  231.1 21.13 180 top
C695  22uF  [CC0603N]  232.08 86.33 0 top
C696  22uF  [CC0603N]  232.01 81.33 0 bottom
C697  22uF  [CC0603N]  201.12 92.08 270 top
C698  22uF  [CC0603N]  232.01 78.78 0 bottom
C699  22uF  [CC0603N]  200.56 97.89 90 bottom
C700  22uF  [CC0603N]  232.02 77.54 0 top
C701  22uF  [CC0603N]  179.93 73.73 180 bottom
C702  10uF  [CC0603N]  232.1 88.76 0 top
C703  10uF  [CC0603N]  227.75 70.57 270 top
C704  10uF  [CC0603N]  232.01 80.02 0 top
C705  10uF  [CC0603N]  230.26 70.55 270 top
C706  10uF  [CC0603N]  199.21 97.9 90 bottom
C707  10uF  [CC0603N]  232.01 72.61 0 top
C708  10UF  [CC0603N]  194.59 92.52 270 top
C709  10UF  [CC0603N]  179.92 75.02 180 bottom
C710  10UF  [CC0603N]  210.87 97.7 90 bottom
C711  10UF  [CC0603N]  193.35 92.14 270 top
C712  10UF  [CC0603N]  205.79 92.21 270 top
C713  10UF  [CC0603N]  190.86 92.38 270 top
C714  1uF  [CC0402N]  218.3 70.12 90 bottom
C715  1uF  [CC0402N]  218.67 74.66 180 bottom
C716  1uF  [CC0402N]  219.16 70.07 90 bottom
C717  1uF  [CC0402N]  212.79 72.44 90 bottom
C718  1uF  [CC0402N]  216.28 80.77 270 bottom
C719  1uF  [CC0402N]  218.64 76.59 180 bottom
C720  1uF  [CC0402N]  196.18 70.68 90 bottom
C721  1uF  [CC0402N]  196.98 70.68 90 bottom
C722  1uF  [CC0402N]  216.51 69.98 90 bottom
C723  1uF  [CC0402N]  220.25 70.51 90 bottom
C724  1uF  [CC0402N]  183.56 68.81 90 bottom
C725  1uF  [CC0402N]  184.6 68.8 90 bottom
C726  1uF  [CC0402N]  181.7 68.77 90 bottom
C727  1uF  [CC0402N]  218.13 80.64 270 bottom
C798  10UF  [CC0603N]  14 110.67 270 top
C877  0.1u  [CC0402N]  140.37 68.05 180 top
C878  0.1u  [CC0402N]  137.11 68.05 180 top
C879  10UF  [CC0603N]  226.1 8.76 270 bottom
C880  10UF  [CC0603N]  224.84 8.78 270 bottom
C881  1uF  [CC0402N]  227.86 8.93 90 bottom
C882  1uF  [CC0402N]  227.07 8.93 90 bottom
C883  0.1uF  [CC0402N]  230.12 28.1 270 bottom
C884  2.2uF  [CC0603N]  228.75 28.36 270 bottom
C885  0.1uF  [CC0402N]  202.44 31.43 180 bottom
C886  2.2uF  [CC0603N]  202.51 32.44 180 bottom
C887  0.1uF  [CC0402N]  184.74 33.84 90 bottom
C888  10UF  [CC0603N]  211.49 25.92 270 bottom
C889  10UF  [CC0603N]  200.01 23.77 90 bottom
C890  10UF  [CC0603N]  163.46 26.23 90 bottom
C891  10UF  [CC0603N]  221.42 25.44 90 bottom
C892  10UF  [CC0603N]  217.03 20.05 180 bottom
C893  10UF  [CC0603N]  173.75 29.22 270 bottom
C894  10UF  [CC0603N]  162.25 30.47 270 bottom
C895  10UF  [CC0603N]  192.03 30.15 0 bottom
C896  1uF  [CC0402N]  169.87 26.63 90 bottom
C897  1uF  [CC0402N]  201.15 26.22 270 bottom
C898  1uF  [CC0402N]  178.75 30.43 270 bottom
C899  1uF  [CC0402N]  189.37 32.49 270 bottom
C900  1uF  [CC0402N]  190.35 28.5 180 bottom
C901  1uF  [CC0402N]  175.04 29.36 270 bottom
C902  1uF  [CC0402N]  198.97 24.03 90 bottom
C903  1uF  [CC0402N]  178.41 25.76 270 bottom
C904  10UF  [CC0603N]  225.76 13.54 0 bottom
C905  0.1uF  [CC0402N]  225.37 17.02 0 bottom
C906  0.1uF  [CC0402N]  225.38 16.24 0 bottom
C907  0.1uF  [CC0402N]  225.37 14.62 0 bottom
C908  0.1uF  [CC0402N]  225.37 15.44 0 bottom
C3218  0.1uF_25V_0603  [CC0603N]  99.69 109.25 90 bottom
C6036  10UF  [CC0603N]  22.18 108.65 180 top
C6037  10UF  [CC0603N]  22.18 107.43 180 top
C6038  0.01uF  [CC0402N]  67.32 76.36 0 top
C6039  0.01uF  [CC0402N]  70.52 75.88 90 top
C6040  0.01uF  [CC0402N]  73.49 75.88 90 top
C6041  0.01uF  [CC0402N]  76.97 76.38 180 top
C6056  10UF  [CC0603N]  233.1 19.19 0 bottom
C6057  10UF  [CC0603N]  231.85 37.94 0 top
C6058  10UF  [CC0603N]  232.8 64.34 0 bottom
C6059  0.1uF  [CC0402N]  209.05 89.4 270 top
C6060  0.1uF  [CC0402N]  209.83 89.41 270 top
C6061  0.1uF  [CC0402N]  211.65 89.67 225 top
C6062  0.1uF  [CC0402N]  211.12 90.2 225 top
C6064  0.01uF_25V_0402  [C0402]  100.84 109.53 270 bottom
C6112  22uF  [CC0603N]  231.97 83.85 0 bottom
C6113  22uF  [CC0603N]  204.44 92.41 270 top
C6114  47uF  [CC0805N]  202.7 92.47 270 top
C6115  47uF  [CC0805N]  197.52 97.49 90 bottom
C6116  47uF  [CC0805N]  213.74 97.65 90 bottom
C6117  47uF  [CC0805N]  231.8 91.86 0 top
C6118  10UF  [CC0603N]  232.09 88.76 0 bottom
C6119  10UF  [CC0603N]  232.01 82.58 0 top
C6120  10UF  [CC0603N]  207.08 92.2 270 top
C6121  220pF  [CC0603N]  9.42 110.33 270 top
C6122  220pF  [CC0603N]  9.44 113.44 90 top
C6123  220pF  [CC0603N]  227.06 113.22 90 top
C6124  220pF  [CC0603N]  227.07 110.49 270 top
C6125  220pF  [CC0603N]  151.44 112.32 270 top
C6126  1uF  [CC0402N]  219.02 71.3 90 top
C6128  1uF  [CC0402N]  188.52 87.97 0 top
C6129  22uF  [CC0603N]  154.41 91.33 90 top
C6130  1uF  [CC0402N]  155.92 92.92 0 top
C6131  22uF  [CC0603N]  187.84 90.12 90 top
C6132  1uF  [CC0402N]  188.32 85.41 270 bottom
C6133  10uF_50V_1206  [CC1206N]  110.79 103.62 180 top
C6134  0.1uF  [CC0402N]  162.7 101.96 270 bottom
C6135  0.1uF  [CC0402N]  163.17 110.4 90 top
C6136  0.1uF  [CC0402N]  215.89 84.55 270 bottom
C6137  0.1uF  [CC0402N]  226.08 92.53 270 bottom
C6138  1uF  [CC0402N]  185.74 88.61 0 bottom
C6139  0.1uF  [CC0402N]  185.74 87.81 0 bottom
C6140  0.1uF  [CC0402N]  163.63 77.26 180 top
C6147  0.1u  [CC0402N]  19.09 113.01 180 top
C6148  0.1u  [CC0402N]  37.17 107.69 90 top
C6154  0.1u  [CC0402N]  51.79 98.59 180 bottom
C6155  0.1u  [CC0402N]  53.67 109 0 top
C6156  0.1u  [CC0402N]  122.77 48.34 180 bottom
C6158  10uF_50V_1206  [CC1206N]  232.11 66.26 0 bottom
C6159  47uF  [CC0805N]  233.09 17.77 0 bottom
C6160  10UF  [CC0603N]  231.88 39.19 0 top
CN2  F2G10U-A1T1-E  [SMD-CN-50P-10N-H]  130.91 55.99 90 bottom
CN3  099AADB19FBXCNA  [SMD-HDMI-CN-50P-19BN]  59.15 99.1 90 top
CN4  CN2+2-S  [SMD-CN-200P-2N-H]  56.79 12.65 180 top
CN5  BS-06-A3A0J001  [SMD-BATTERY-2900P-2N]  197.64 45.03 180 bottom
CN6  1.25T-2-2PWB-T  [SMD-CN-125P-2WBN]  4.27 111.91 270 top
CN7  CDZ-1.7-V10-2010  [TH-DCIN-540P-3N]  89.65 99.1 180 top
CN8  1.25T-2-2PWB-T  [SMD-CN-125P-2WBN]  232.2 111.69 90 top
CN9  SAF-2001BB-41-5N  [TH-SATA-127P-22AN-R-KX]  13.94 57.11 270 top
CN10  213MAAA32  [SMD-M2PCIE-50X750P-75BN]  104.12 64.97 270 top
CN11  ASAA821-H4SB5-7H  [SMD-DDR4-50X820P-260N-L]  192.6 28.15 180 top
CN12  AFA04-S05ECA-00  [SMD-FPC-100P-5N-H]  144.76 45.82 0 top
CN13  WB1012US-04T5  [SMD-CN-100P-4N-V-CB]  230.87 30.8 270 top
CN14  071CAAAZ40B  [SMD-CN-80X820P-52DN-RN]  227.84 39 270 bottom
CN15  WB1012US-04T5  [SMD-CN-100P-4N-V-CB]  232.45 63.99 90 top
CN19  ASAA821-E8SB0-7H  [SMD-DDR4-50X820P-260N-9L]  192.6 16.61 180 top
CN20  P5C08F-401665-XX  [SMD-CN-200P-8N]  26.95 41.28 270 top
CN21  WB1003UR-40XXB  [SMD-CN-100P-40AN-H]  40.14 23.23 270 top
CN22  M.2 SOCKET-1 SD/DP KEY E  [SMD-M2PCIE-50X750P-75AN]  136.88 99.36 270 top
CP2  330uF  [CCP7343N]  138.78 53.7 90 top
CP3  330uF  [CCP7343N]  133.71 53.7 90 top
CP4  150UF  [CAE630W570HN]  93.59 80.36 0 top
CP5  150UF  [CAE630W570HN]  137.95 80.32 90 top
CP7  47UF  [CAE630W570HN]  103.03 106.98 270 top
CP10  330uF  [CCP7343N]  169.93 100.45 90 top
CP11  100uF  [CAE660W800HN]  55.08 43.63 180 top
CP12  10UF  [THR-CPR50-630X1100N]  66.64 16.19 0 top
CP13  10uF  [CAE6800W1000HN]  66.86 14.82 0 top
CP18  330uF  [CCP7343N]  199.66 100.35 90 top
CP19  330uF  [CCP7343N]  182.43 93.78 180 top
CP20  330uF  [CCP7343N]  204.89 100.4 90 top
D1  LBAT54HT1G  [SOD1713N]  177.09 43.4 0 bottom
D2  SK34L  [SOD5225N]  96.86 95.55 270 top
D3  LBAT54HT1G  [SOD1713N]  178.62 46 180 bottom
D4  D_2PN  [SOT95P280-3N]  62.68 93.99 180 bottom
D5  D_2PN  [SOT95P280-3N]  85 87.79 0 top
D6  D_2PN  [SOT95P280-3N]  85.94 91.16 0 top
D7  LMDL914T1G  [SOD1713N]  58.69 88.64 90 bottom
D16  D_2PN  [SOT95P280-3N]  58.98 98.86 270 bottom
D19  1SS355TE17  [SOD2514N]  87.27 111.5 90 top
D20  1SS355TE17  [SOD2514N]  89.19 111.5 90 top
D21  AOZ8231  [SOD0806N]  20.21 104.92 90 bottom
D22  AOZ8231  [SOD0806N]  20.21 103.08 270 bottom
D25  1SS355TE17  [SOD2514N]  231.77 19.76 0 top
D26  BAT54SLT1G  [SOT95P280-3N]  61.5 86.91 90 top
D27  AOZ8231  [SOD0806N]  24.75 98.67 270 bottom
D28  AOZ8231  [SOD0806N]  24.76 100.54 90 bottom
D29  ESD0524VA  [DFN2510P10E]  31.48 98.61 270 bottom
D32  AOZ8231  [SOD0806N]  145.67 47.51 0 top
D33  AOZ8231  [SOD0806N]  143.87 47.51 180 top
D34  AOZ8231  [SOD0806N]  45.24 90.48 180 top
D35  AOZ8231  [SOD0806N]  47.09 90.49 0 top
D36  AOZ8231  [SOD0806N]  41.31 100.06 90 bottom
D37  AOZ8231  [SOD0806N]  41.31 98.2 270 bottom
D38  1SS355TE17  [SOD2514N]  219.93 34.67 180 bottom
D45  ESD0524VA  [DFN2510P10E]  20.69 99.11 270 bottom
D46  B2100  [SOD5336N]  66.83 31.07 180 top
D48  ESD0524VA  [DFN2510P10E]  52.69 89.59 0 top
D49  ESD0524VA  [DFN2510P10E]  55.67 89.59 180 top
D50  DFLS1100-7  [SOD2818N]  66.55 31.06 180 top
D52  AOZ8231  [SOD0806N]  6.07 94.48 270 bottom
D53  AOZ8231  [SOD0806N]  5.92 104.49 90 bottom
D54  AOZ8231  [SOD0806N]  13 92.97 90 top
D55  AOZ8231  [SOD0806N]  3.87 93.45 90 bottom
D56  AOZ8231  [SOD0806N]  12.53 102.47 0 top
D57  AOZ8231  [SOD0806N]  2.06 99.19 270 top
D58  TPA323HL  [SOD0808N]  98.12 109.16 270 bottom
D59  AOZ8231  [SOD0806N]  8.29 112.99 90 top
D60  AOZ8231  [SOD0806N]  8.29 110.83 270 top
D61  AOZ8231  [SOD0806N]  228.19 110.86 270 top
D62  AOZ8231  [SOD0806N]  228.19 112.67 90 top
D64  LMDL914T1G  [SOD1713N]  19.32 89.21 180 top
D65  AOZ8231  [SOD0806N]  150.25 113.2 90 top
D66  1SS355TE17  [SOD2514N]  146.82 92.21 90 bottom
D67  1SS355TE17  [SOD2514N]  168.36 54.81 180 bottom
D68  1SS355TE17  [SOD2514N]  146.74 87.45 90 bottom
D69  1SS355TE17  [SOD2514N]  151.4 83.34 270 bottom
D70  1SS355TE17  [SOD2514N]  149.19 76.33 180 bottom
D71  1SS355TE17  [SOD2514N]  149.17 78.25 180 bottom
D72  1SS355TE17  [SOD2514N]  91.09 111.43 90 top
D73  1SS355TE17  [SOD2514N]  91.71 110.07 0 bottom
DR1  100k  [RC0402N]  232.65 49.35 180 top
F1  1206L110//NANOSMDC110F  [F1206N]  122.08 51.96 0 bottom
F2  1206L110//NANOSMDC110F  [F1206N]  17.87 109.38 0 top
F3  1206L110//NANOSMDC110F  [F1206N]  39.72 110.91 180 top
F5  1206L110//NANOSMDC110F  [F1206N]  56.04 99.94 270 bottom
F6  1206L110//NANOSMDC110F  [F1206N]  54.1 112.6 180 top
F7  0.5A  [F1206N]  59.92 49.41 0 top
F8  1206_8A  [F1206N]  100.72 97.15 180 top
FB1  120  [FB0805N]  123.19 90.98 180 bottom
FB2  120  [FB0805N]  99.62 100.05 270 top
FB3  180  [FB0603N]  54.71 31.88 180 top
FB4  120  [FB0805N]  123.33 75.41 90 bottom
FB5  120  [FB0805N]  124.94 75.41 90 bottom
FB6  120.0 ohm  [FB0603N]  97.35 75.64 90 top
FB7  120  [FB0805N]  101.29 100.03 270 top
FB8  120.0 ohm  [FB0603N]  96.14 75.63 90 top
FB9  180  [FB0603N]  54.7 30.61 180 top
FB10  120  [FB0805N]  102.89 100.03 270 top
FB11  180  [FB0603N]  61.08 26.71 270 bottom
FB12  180  [FB0603N]  59.62 19 270 bottom
FB13  120.0 ohm  [FB0603N]  44.4 80.55 90 bottom
FB14  120.0 ohm  [FB0603N]  21.61 56.62 270 top
FB15  120.0 ohm  [FB0603N]  233.24 24.98 90 top
FB16  120.0 ohm  [FB0603N]  132.21 66.72 90 bottom
FB17  120.0 ohm  [FB0603N]  23.91 74.15 270 top
FB18  180  [FB0603N]  60.3 21 0 bottom
FB21  120.0 ohm  [FB0603N]  22.83 56.62 270 top
FB22  120.0 ohm  [FB0603N]  18.09 84.91 0 top
FB24  120.0 ohm  [FB0603N]  27.67 71.21 180 top
FB25  120.0 ohm  [FB0603N]  27.67 70 180 top
FB26  120.0 ohm  [FB0603N]  33.45 72.75 270 top
FB27  120.0 ohm  [FB0603N]  25.62 88.89 270 top
FB28  120.0 ohm  [FB0603N]  36.75 70.99 270 top
FB30  120.0 ohm  [FB0603N]  35.87 73.06 0 top
FB31  120.0 ohm  [FB0603N]  35.87 74.3 0 top
FB34  120.0 ohm  [FB0603N]  20.07 85.26 270 top
FB35  120.0 ohm  [FB0603N]  21.29 85.26 270 top
FB36  120  [FB0805N]  93 109.51 270 top
FB37  120  [FB0805N]  94.6 109.51 270 top
FB38  120.0 ohm  [FB0603N]  24.39 88.89 270 top
FB39  120  [FB0805N]  154.22 88.14 270 top
FB40  120  [FB0805N]  189.36 90.53 270 top
FB41  120  [SFB1206A]  157.58 90.09 0 top
FB42  120  [SFB1206A]  162.74 50.76 0 bottom
FB43  120  [SFB1206A]  158.75 94.09 0 top
FIL1  330mA  [FIL_175P200X120-4L]  22.13 104.01 90 bottom
FIL2  330mA  [FIL_175P200X120-4L]  23.39 94.04 0 bottom
FIL3  330mA  [FIL_175P200X120-4L]  20.89 94.07 0 bottom
FIL4  330mA  [FIL_175P200X120-4L]  46.16 88.52 180 top
FIL5  330mA  [FIL_175P200X120-4L]  50.89 84.62 180 top
FIL6  330mA  [FIL_175P200X120-4L]  53.38 84.63 180 top
FIL7  330mA  [FIL_175P200X120-4L]  55.92 84.62 180 top
FIL8  330mA  [FIL_175P200X120-4L]  58.43 84.63 180 top
FIL9  330mA  [FIL_175P200X120-4L]  32.48 102.14 90 bottom
FIL10  330mA  [FIL_175P200X120-4L]  34.28 94.82 0 bottom
FIL11  330mA  [FIL_175P200X120-4L]  31.67 93.98 0 bottom
FIL13  330mA  [FIL_175P200X120-4L]  144.75 49.46 180 top
FIL14  330mA  [FIL_175P200X120-4L]  43.24 99.14 90 bottom
FIL15  330mA  [FIL_175P200X120-4L]  69.02 91.13 0 bottom
FIL16  330mA  [FIL_175P200X120-4L]  66.94 97.07 0 bottom
FIL17  330mA  [FIL_175P200X120-4L]  73.67 97.1 0 bottom
FIL18  330mA  [FIL_175P200X120-4L]  74.03 102 90 bottom
J1  CN-USB-9+2  [TH-USB-200X150P-9KN]  16.24 99.15 90 top
J2  CN-USB-9+2  [TH-USB-200X150P-9KN]  26.96 99.15 90 top
J4  SHNG04X-XX-XX-XXX  [TH-USB-250PX200P-4BN]  48.9 99.15 90 top
J5  SHNG04X-XX-XX-XXX  [TH-USB-250PX200P-4BN]  38.17 99.15 90 top
J7  PJ-358A  [TH-EARPHONE-330X400P-5N]  6 94.6 180 top
J8  PJ-358A  [TH-EARPHONE-330X400P-5N]  6 104.1 180 top
J9  Header_1X3  [SHDR1X3_254-HB11031]  98.22 49.52 180 top
L2  1.0uH  [LC6666N]  84.76 81.5 270 top
L3  1.0uH  [LC6666N]  130.7 80.4 270 top
L6  1.0uH  [LC6666N]  127.31 55.55 270 top
L7  1.0uH  [LC6666N]  147.08 90.21 0 top
L8  2.2uH  [LC3030DL]  66.39 66.62 180 bottom
L9  10uH  [LC6666N]  65.89 44.4 0 top
L10  2.2uH  [LC3030DL]  55.8 19 90 bottom
L18  2.2uH  [LC4040L]  151.34 76.79 0 top
LC1  330pF  [CC0402N]  65.7 101.44 180 bottom
LC2  1000pF  [CC0402N]  65.7 100.62 180 bottom
LED2  27-21/BHC-AN1P2/3C  [LED1706N]  124.92 115.24 0 top
LFB1  47  [FB0603N]  65.53 104.95 0 bottom
LFB2  47  [FB0603N]  65.53 103.7 0 bottom
LFB3  47  [FB0603N]  65.53 102.47 0 bottom
LJ1  RJB-2X08X-XX-XX-XXX  [TH-RJ45-127P-8N]  77.75 99.1 90 top
LPM1  0.22uH  [LC7266N]  193.24 101.25 0 top
LPM2  0.22uH  [LC7266N]  184.04 101.21 0 top
LPM3  0.22uH  [LC7266N]  212.96 99.63 0 top
LPM5  0.22uH  [LC7266N]  160.36 99.46 90 top
MARK1  MARK  [MARK-D100D250]  17.07 9.67 0 top
MARK2  MARK  [MARK-D100D250]  233.12 105.67 0 top
MARK3  MARK  [MARK-D100D250]  228.89 8.76 0 top
MARK4  MARK  [MARK-D100D250]  32.5 113.66 0 top
MARK5  MARK  [MARK-D100D250]  17.09 9.66 180 bottom
MARK6  MARK  [MARK-D100D250]  229.83 8.57 180 bottom
MARK7  MARK  [MARK-D100D250]  232.3 114.81 180 bottom
MARK8  MARK  [MARK-D100D250]  7.32 111.48 180 bottom
MH1  H  [MTG230H500]  29.55 110.6 0 top
MH2  H  [MTG230H500]  179.19 114.09 0 top
MH3  H  [MTG230H500]  231.7 12.1 0 top
MH4  H  [MTG220H400]  136.05 114 180 bottom
MH5  H  [MTG380H500]  160.66 63.92 270 top
MH6  H  [MTG380H500]  224.94 85.07 180 top
MH7  H  [MTG380H500]  160.66 85.07 270 top
MH8  H  [MTG380H500]  224.94 63.92 180 top
MH9  H  [MTG340H580_TOP]  107.49 99.37 90 top
MH10  H  [MTG220H400]  80.25 114 180 bottom
MH11  H  [MTG380H600]  24.33 64.98 0 top
MH12  H  [MTG380H600]  24.95 24.1 0 top
MH13  H  [MTG380H600]  151.15 24.1 0 top
MQ1  SM7302ESKP  [KPAK127P605-9N]  118.14 57.64 270 top
NOREF  -  [unnamed]  229.8 2.5 0 top
NOREF#2  -  [unnamed]  229.8 120.2 0 top
NOREF#3  -  [unnamed]  5 120.2 0 top
NOREF#4  -  [unnamed]  5 2.5 0 top
NS2  VIA  [NET_SHORT]  215.24 102.6 90 top
PC1  4.7UF  [CC0603N]  198.07 113.91 90 top
PC2  4.7UF  [CC0603N]  200.48 113.92 90 top
PC3  4.7UF  [CC0603N]  199.27 113.91 90 top
PC4  4.7UF  [CC0603N]  202.91 113.92 90 top
PC5  1uF  [CC0603N]  201.7 113.92 90 top
PC6  4.7UF  [CC0603N]  172.47 112.89 90 top
PC7  2200pF  [CC0402N]  196.19 113.8 0 top
PC8  0.1uF  [CC0402N]  221.29 108.25 270 bottom
PC10  0.1uF  [CC0603N]  230.55 100.37 0 bottom
PC11  0.1uF  [CC0603N]  230.4 104.1 0 bottom
PC12  0.1uF  [CC0402N]  210.73 103.13 0 bottom
PC13  1uF  [CC0402N]  221.65 98.46 0 bottom
PC14  1uF  [CC0603N]  206.26 106.22 0 bottom
PC15  0.22uF  [CC0603N]  227.06 108.32 90 bottom
PC16  4.7UF  [CC0603N]  171.27 112.89 90 top
PC17  1uF  [CC0603N]  176.09 112.89 90 top
PC18  1uF  [CC0402N]  228.88 107.01 180 bottom
PC20  2200pF  [CC0402N]  177.49 102.78 180 top
PC21  0.1uF  [CC0402N]  219.21 110.23 270 bottom
PC22  120pF  [CC0402N]  219.18 104.16 180 bottom
PC23  220pF  [CC0402N]  217.08 104.19 270 bottom
PC24  4.7UF  [CC0603N]  174.89 112.89 90 top
PC25  4.7UF  [CC0603N]  173.67 112.89 90 top
PC26  4.7UF  [CC0603N]  207.75 113.91 90 top
PC27  1uF  [CC0603N]  204.13 113.92 90 top
PC28  4.7UF  [CC0603N]  208.96 113.91 90 top
PC29  4.7UF  [CC0603N]  206.55 113.91 90 top
PC30  4.7UF  [CC0603N]  205.34 113.91 90 top
PC38  2200pF  [CC0402N]  208.31 101.45 90 top
PC39  0.1uF  [CC0402N]  226.28 112.56 270 bottom
PC42  4.7UF  [CC0603N]  216.18 105.7 0 bottom
PC43  4.7UF  [CC0603N]  148.25 108.76 90 top
PC44  4.7UF  [CC0603N]  147.02 108.75 90 top
PC45  4.7UF  [CC0603N]  149.49 108.76 90 top
PC48  4.7UF  [CC0603N]  144.52 108.72 90 top
PC49  1uF  [CC0603N]  145.76 108.72 90 top
PC50  0.1uF  [CC0402N]  166.63 101.86 180 bottom
PC51  2200pF  [CC0402N]  150.94 102.25 0 top
PC52  0.47uF  [CC0402N]  158.38 98.45 90 bottom
PC54  27pF  [CC0402N]  156.88 101.24 180 bottom
PC55  4.7UF  [CC0603N]  161.34 94.45 180 bottom
PC56  4.7UF  [CC0603N]  220.13 98.02 270 bottom
PC57  0.47uF  [CC0402N]  216.96 101.34 180 bottom
PC58  0.1uF  [CC0402N]  219.7 108.24 270 bottom
PC59  0.1uF  [CC0402N]  221.25 110.24 270 bottom
PC61  0.1uF  [CC0402N]  227.92 112.56 270 bottom
PC62  2200pF  [CC0402N]  156.89 102.05 180 bottom
PC63  27pF  [CC0402N]  158.71 102.05 180 bottom
PC64  10UF  [CC0603N]  177.21 94.14 0 bottom
PC65  10UF  [CC0603N]  174.29 84.75 270 bottom
PC66  10UF  [CC0603N]  166.65 92.43 270 top
PC67  10UF  [CC0603N]  176.3 92.3 315 top
